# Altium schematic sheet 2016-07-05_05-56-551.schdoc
size 326 x 125 mm; SheetNumber: 1; SheetTotal: 1
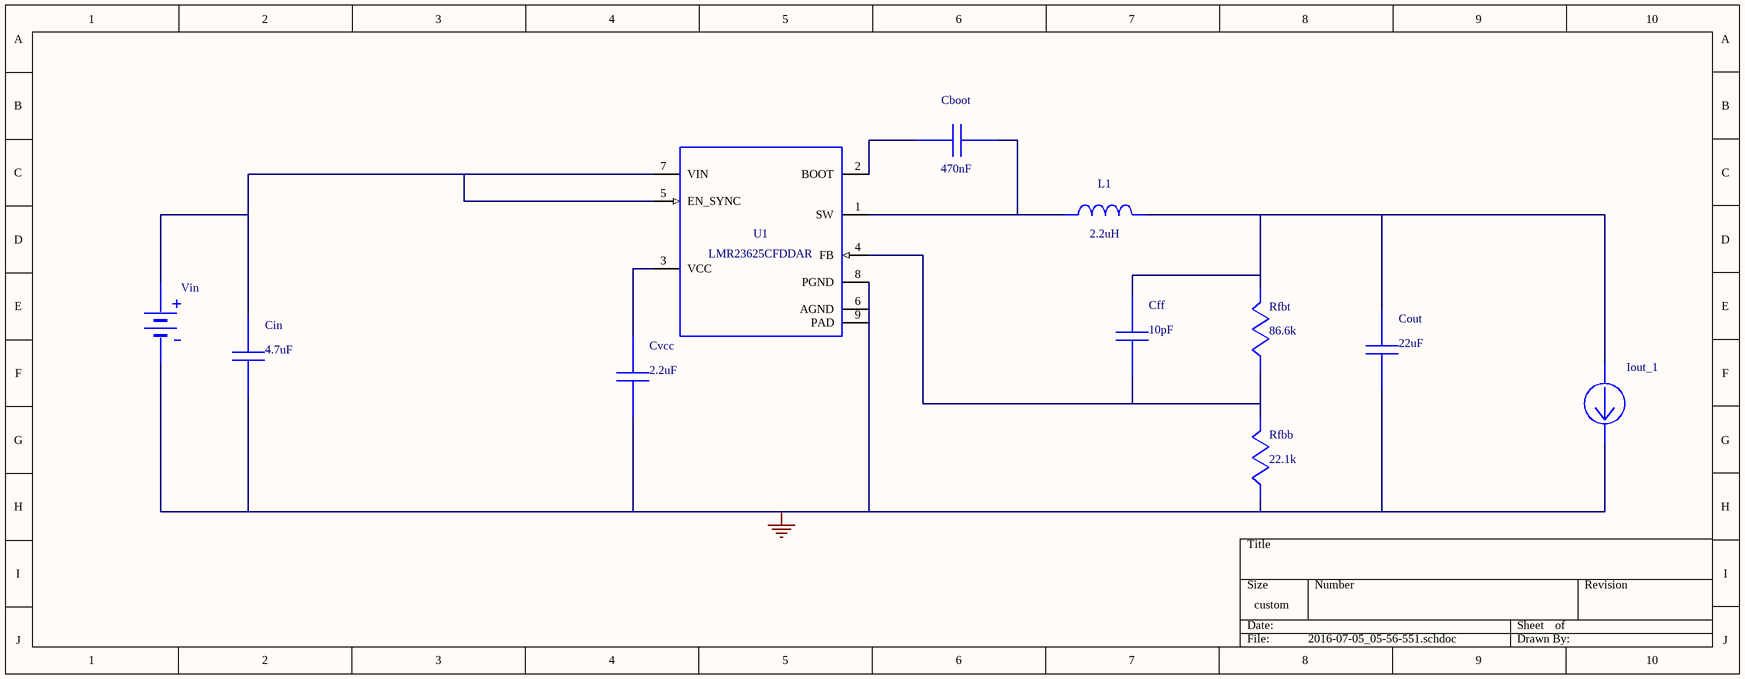
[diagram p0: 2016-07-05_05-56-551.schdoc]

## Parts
Cboot  value 470nF  (hidden comment: GRM21BR72A474KA73L)
Cff  value 10pF  (hidden comment: CL02C100JO2ANNC)
Cin  value 4.7uF  (hidden comment: GRM32ER71H475KA88L)
Cout  value 22uF  (hidden comment: GRM32ER61C226ME20L)
Cvcc  value 2.2uF  (hidden comment: GRM155R60J225ME15D)
Iout_1  WB_CURRENT_LOAD  (value not drawn)
L1  value 2.2uH  (hidden comment: XFL4020-222MEB)
Rfbb  value 22.1k  (hidden comment: CRCW040222K1FKED)
Rfbt  value 86.6k  (hidden comment: CRCW040286K6FKED)
U1  LMR23625CFDDAR
Vin  WB_BATTERY  (value not drawn)

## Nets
0: Cin.2 Cout.2 Cvcc.2 Iout_1.2(-) Rfbb.2 U1.6(AGND) U1.8(PGND) U1.9(PAD) Vin.2(-)
NetCboot_1: Cboot.1 U1.2(BOOT)
NetCboot_2: Cboot.2 L1.1 U1.1(SW)
NetCff_1: Cff.1 Cout.1 Iout_1.1(+) L1.2 Rfbt.1
NetCff_2: Cff.2 Rfbb.1 Rfbt.2 U1.4(FB)
NetCin_1: Cin.1 U1.5(EN_SYNC) U1.7(VIN) Vin.1(+)
NetCvcc_1: Cvcc.1 U1.3(VCC)

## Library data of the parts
Cboot = GRM21BR72A474KA73L: GRM21BR72A474KA7; Manufacturer Name: MuRata
Cff = CL02C100JO2ANNC: Manufacturer Name: Samsung Electro-Mechanics
Cin = GRM32ER71H475KA88L: GRM32ER71H475KA8; Manufacturer Name: MuRata
Cout = GRM32ER61C226ME20L: GRM32ER61C226ME2; Manufacturer Name: MuRata
Cvcc = GRM155R60J225ME15D: GRM155R60J225ME1; Manufacturer Name: MuRata
L1 = XFL4020-222MEB: Manufacturer Name: Coilcraft
Rfbb = CRCW040222K1FKED: Manufacturer Name: Vishay-Dale
Rfbt = CRCW040286K6FKED: Manufacturer Name: Vishay-Dale
U1 = LMR23625CFDDAR: Manufacturer Name: Texas Instruments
